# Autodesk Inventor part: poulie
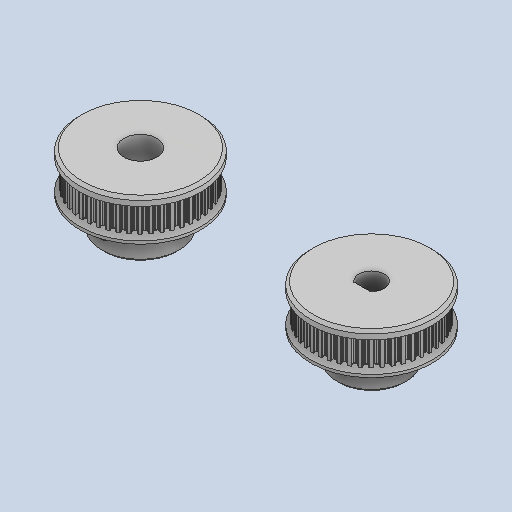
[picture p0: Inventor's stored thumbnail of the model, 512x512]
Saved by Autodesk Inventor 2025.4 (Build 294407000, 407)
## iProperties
Created: 2026-06
Part Number: poulie
Material: Generic
Document SubType Name: Modeling
Designer: AdminForWorker
Density: 1 g/cm^3
Appearance: Default
Title: poulie v5
Author: AdminForWorker
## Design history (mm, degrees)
feature "Poulie_Tapis"
feature "Poulie_Moteur"
body "Solid1"
body "Solid2"
